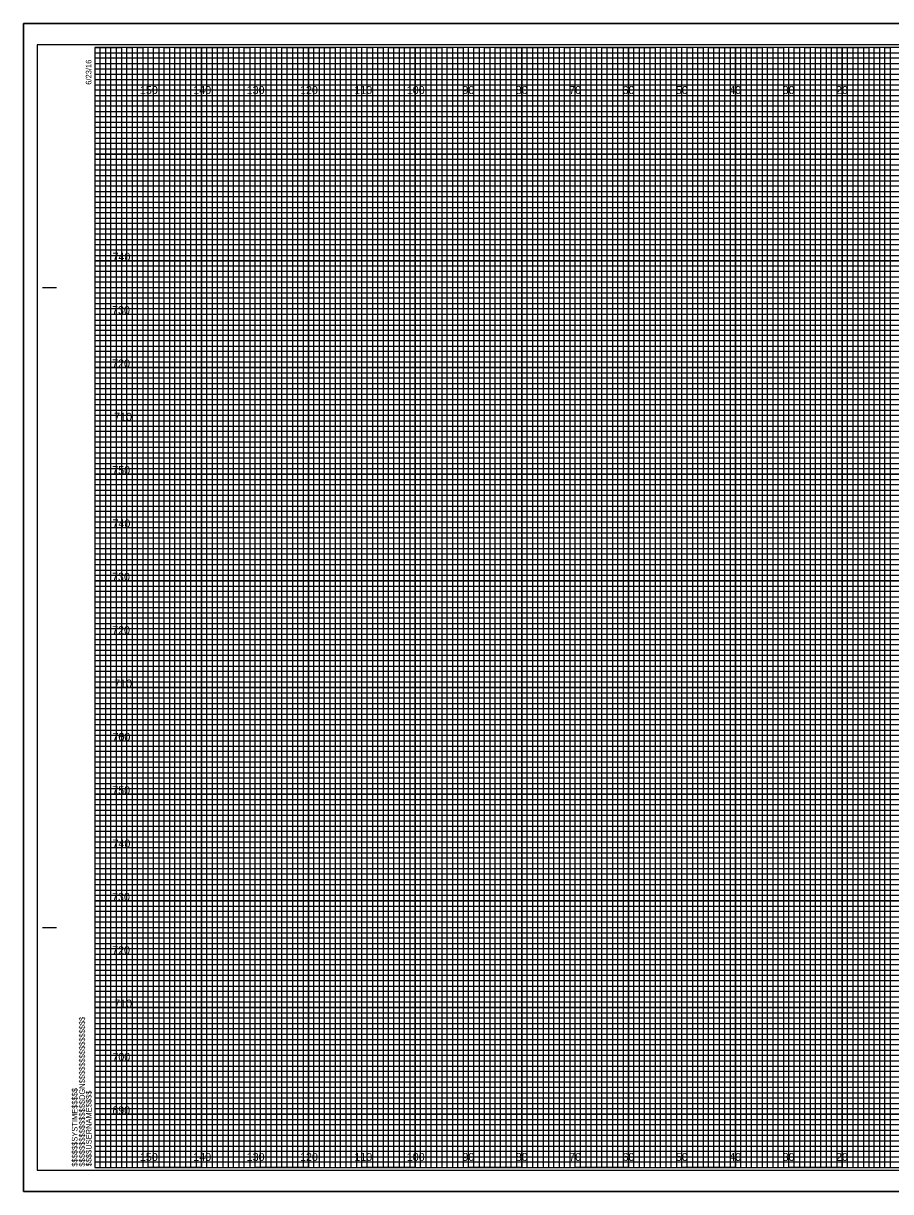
# Model space of a CAD drawing. Extents: x -98 to 717, y -10 to 1974.
# Drawn here: x -13.4 to 149.1, y 1315.5 to 1534.5 of the extents above; entities that cross this region are included whole.
import ezdxf

# ---------------------------------------------------------------- set-up
doc = ezdxf.new("R2010")
doc.units = 0
for name, color, linetype in [('Default', 7, 'Continuous'), ('Exist XS Center Line Elevation Label', 7, 'Continuous'), ('Prop CMT Conc Surface', 7, 'Continuous'), ('Prop CMT Concrete Structures', 7, 'Continuous'), ('Prop CMT Pvmt Course 1 CG', 7, 'Continuous'), ('Prop CMT Pvmt Course 2', 7, 'Continuous'), ('Prop CMT Pvmt Course 3', 7, 'Continuous'), ('Prop CMT Pvmt Surface', 7, 'Continuous'), ('Prop CMT Subgrade Earthwork', 7, 'Continuous'), ('Prop XS Earthwork Shape', 7, 'Continuous'), ('Prop XS Elevation Labels', 7, 'Continuous'), ('Typical Curb CELL', 7, 'Continuous')]:
    doc.layers.add(name, color=color, linetype=linetype)

msp = doc.modelspace()

# ---------------------------------------------------------------- linework, layer by layer
at = {"layer": 'Default'}
msp.add_lwpolyline([(323.3, 1315.5), (-13.4, 1315.5), (-13.4, 1534.5), (323.3, 1534.5)], close=True, dxfattribs=at)
at = {"layer": 'Exist XS Center Line Elevation Label'}
for p, q in [((0, 1529), (260, 1529)), ((260, 1527.98), (0, 1527.98)), ((0, 1527.98), (0, 1527)), ((0, 1527), (260, 1527)), ((260, 1525.89), (0, 1525.89)), ((0, 1525.89), (0, 1524)), ((0, 1524), (320, 1524))]:
    msp.add_line(p, q, dxfattribs=at)
for points in [[(0, 1523), (270, 1523), (320, 1523), (320, 1522), (0, 1522)], [(0, 1521), (320, 1521), (320, 1519), (0, 1519)], [(0, 1518), (320, 1518), (320, 1517), (0, 1516.98)], [(0, 1516), (320, 1516), (320, 1514), (0, 1514)], [(0, 1513), (320, 1513), (320, 1512), (0, 1512)], [(0, 1511), (320, 1511), (320, 1509), (0, 1509)], [(0, 1508), (320, 1508), (320, 1507), (0, 1507)], [(0, 1506), (320, 1506), (320, 1504), (0, 1504)], [(0, 1503), (320, 1503), (320, 1502), (0, 1502)], [(0, 1501), (320, 1501), (320, 1499), (0, 1499)], [(0, 1498), (320, 1498), (320, 1497), (0, 1497)], [(0, 1496), (320, 1496), (320, 1493.95), (320, 1493), (320, 1492), (0, 1492)], [(0, 1494), (320, 1494), (320, 1493), (0, 1493)], [(0, 1491), (320, 1491), (320, 1489), (0, 1489.03)], [(0, 1489.03), (320, 1489), (320, 1488), (0, 1488)], [(0, 1487), (320, 1487), (320, 1486), (0, 1486)], [(0, 1484), (320, 1484), (320, 1483), (0, 1483)], [(0, 1482), (320, 1482), (320, 1481), (0, 1481)], [(-0.07, 1478.89), (320, 1478.89), (320, 1477.88), (-0.07, 1477.88)], [(0, 1477), (320, 1477), (320, 1476), (0, 1476)], [(0, 1474), (320, 1474), (320, 1473), (0, 1473)], [(0, 1472), (320, 1472), (320, 1471), (0, 1471)], [(0, 1469), (320, 1469), (320, 1468), (0, 1468)], [(0, 1467), (320, 1467), (320, 1466), (0, 1466)], [(0, 1464), (320, 1464), (320, 1463), (0, 1463)], [(0, 1462), (320, 1462), (320, 1461), (0, 1461)], [(0, 1459), (320, 1459), (319.99, 1457.98), (0, 1458)], [(0, 1457), (320, 1457), (320, 1456), (0, 1456)], [(0, 1454), (320, 1454), (320, 1453), (0, 1453)], [(0, 1452), (320, 1452), (320, 1451), (0, 1451)], [(0, 1449), (320, 1449), (320, 1448), (0, 1448)], [(0, 1447), (320, 1447), (320, 1446), (0, 1446)], [(0, 1444), (320, 1444), (320, 1443), (0, 1443)], [(0, 1442), (320, 1442), (320, 1441), (0, 1441)], [(0, 1439), (320, 1439), (320, 1438), (0, 1438)], [(0, 1436.99), (320.07, 1436.91), (320, 1436), (0, 1436)], [(0, 1434), (320, 1434), (320, 1433), (0, 1433)], [(0, 1432), (320, 1432), (320, 1431), (0, 1431)], [(0, 1429), (320, 1429), (320, 1428), (0, 1428)], [(0, 1427), (320, 1427), (320, 1426), (0, 1426)], [(0, 1424), (320, 1424), (320, 1423), (0, 1423)], [(0, 1422), (320, 1422), (320, 1421), (0, 1421)], [(0, 1419), (320, 1419), (320, 1418), (0, 1418)], [(0, 1417), (320, 1417), (320, 1416), (0, 1416)], [(0, 1414), (320, 1414), (320, 1413), (0, 1413)], [(0, 1412), (320, 1412), (320, 1411), (0, 1411)], [(0, 1409), (320, 1409), (320, 1408), (0, 1408)], [(0, 1407), (320, 1407), (320, 1406), (0, 1406)], [(0, 1404), (320, 1404), (320, 1403), (0, 1403)], [(0, 1402), (320, 1402), (320, 1401), (0, 1401)], [(0, 1399), (320, 1399), (319.99, 1397.98), (0, 1398)], [(0, 1397), (320, 1397), (320, 1396), (0, 1396)], [(0, 1394), (320, 1394), (320, 1393), (0, 1393)], [(0, 1392), (320, 1392), (320, 1391), (0, 1391)], [(0, 1389), (320, 1389), (320, 1388), (0, 1388)], [(0, 1387), (320, 1387), (320, 1386), (0, 1386)], [(0, 1384), (320, 1384), (320, 1383), (0, 1383)], [(0, 1382), (320, 1382), (320, 1381), (0, 1381)], [(0, 1379), (320, 1379), (320, 1378), (0, 1378)], [(0, 1376.99), (320.07, 1376.91), (320, 1376), (0, 1376)], [(0, 1374), (320, 1374), (320, 1373), (0, 1373)], [(0, 1372), (320, 1372), (320, 1371), (0, 1371)], [(0, 1369), (320, 1369), (320, 1368), (0, 1368)], [(0, 1367), (320, 1367), (320, 1366), (0, 1366)], [(0, 1364), (320, 1364), (320, 1363), (0, 1363)], [(0, 1362), (320, 1362), (320, 1361), (0, 1361)], [(0, 1359), (320, 1359), (320, 1358), (0, 1358)], [(0, 1357), (320, 1357), (320, 1356), (0, 1356)], [(0, 1354), (320, 1354), (320, 1353), (0, 1353)], [(0, 1352), (320, 1352), (320, 1351), (0, 1351)], [(0, 1349), (320, 1349), (320, 1348), (0, 1348)], [(0, 1347), (320, 1347), (320, 1346), (0, 1346)], [(0, 1344), (320, 1344), (320, 1343), (0, 1343)], [(0, 1342), (320, 1342), (320, 1341), (0, 1341)], [(0, 1339), (320, 1339), (320, 1338), (0, 1338)], [(0, 1337), (320, 1337), (320, 1336), (0, 1336)], [(0, 1334), (320, 1334), (320, 1333), (0, 1333)], [(0, 1332), (320, 1332), (320, 1331), (0, 1331)], [(0, 1329), (320, 1329), (320, 1328), (0, 1328)], [(0, 1327), (320, 1327), (320, 1326), (0, 1326)], [(0, 1324), (320, 1324), (320, 1323), (0, 1323)], [(0, 1322), (320, 1322), (320, 1321), (0, 1321)]]:
    msp.add_lwpolyline(points, dxfattribs=at)
at = {"layer": 'Prop CMT Conc Surface'}
for p, q in [((-9.8, 1485), (-7.3, 1485)), ((-9.7, 1485), (-7.2, 1485)), ((-9.8, 1365), (-7.3, 1365)), ((-9.7, 1365), (-7.2, 1365)), ((0, 1320), (0, 1320)), ((0, 1320), (0, 1320)), ((0, 1320), (0, 1320)), ((0, 1320), (0, 1320)), ((0, 1320), (0, 1320)), ((0, 1320), (0, 1320)), ((0, 1320), (0, 1320))]:
    msp.add_line(p, q, dxfattribs=at)
msp.add_lwpolyline([(320, 1530), (0, 1530), (0, 1320), (320, 1320)], close=True, dxfattribs=at)
at = {"layer": 'Prop CMT Concrete Structures'}
for p, q in [((10, 1320), (10, 1530)), ((20, 1320), (20, 1530)), ((30, 1320), (30, 1530)), ((40, 1320), (40, 1530)), ((50, 1320), (50, 1530)), ((60, 1320), (60, 1530)), ((70, 1320), (70, 1530)), ((80, 1320), (80, 1530)), ((90, 1320), (90, 1530)), ((100, 1320), (100, 1530)), ((110, 1320), (110, 1530)), ((120, 1320), (120, 1530)), ((130, 1320), (130, 1530)), ((140, 1320), (140, 1530)), ((0, 1520), (320, 1520)), ((0, 1510), (320, 1510)), ((0, 1500), (320, 1500)), ((0, 1490), (320, 1490)), ((0, 1480), (320, 1480)), ((0, 1470), (320, 1470)), ((0, 1460), (320, 1460)), ((0, 1450), (320, 1450)), ((0, 1440), (320, 1440)), ((0, 1430), (320, 1430)), ((0, 1420), (320, 1420)), ((0, 1410), (320, 1410)), ((0, 1400), (320, 1400)), ((0, 1390), (320, 1390)), ((0, 1380), (320, 1380)), ((0, 1370), (320, 1370)), ((0, 1360), (320, 1360)), ((0, 1350), (320, 1350)), ((0, 1340), (320, 1340)), ((0, 1330), (320, 1330))]:
    msp.add_line(p, q, dxfattribs=at)
at = {"layer": 'Prop CMT Pvmt Course 2'}
msp.add_lwpolyline([(-13.4, 1315.5), (323.3, 1315.5), (323.3, 1534.5), (-13.4, 1534.5)], close=True, dxfattribs=at)
at = {"layer": 'Prop CMT Pvmt Course 3'}
msp.add_lwpolyline([(-10.8, 1319.5), (322.4, 1319.5), (322.4, 1530.5), (-10.8, 1530.5)], close=True, dxfattribs=at)
at = {"layer": 'Prop CMT Pvmt Surface'}
for p, q in [((323.3, 1534.5), (-13.4, 1534.5)), ((-13.4, 1534.5), (-13.4, 1315.5)), ((-13.4, 1315.5), (323.3, 1315.5))]:
    msp.add_line(p, q, dxfattribs=at)
at = {"layer": 'Prop CMT Subgrade Earthwork'}
for points in [[(0, 1320), (1, 1320), (1, 1530), (2, 1530), (2, 1320)], [(2, 1320), (3, 1320), (3, 1530), (4, 1530), (4, 1320)], [(5, 1320), (6, 1320), (6, 1530), (7, 1530), (7, 1320)], [(7, 1320), (8, 1320), (8, 1530), (9, 1530), (9, 1320)], [(10, 1320), (11, 1320), (11, 1530), (12, 1530), (12, 1320)], [(12, 1320), (13, 1320), (13, 1530), (14, 1530), (14, 1320)], [(15, 1320), (16, 1320), (16, 1530), (17, 1530), (17, 1320)], [(17, 1320), (18, 1320), (18, 1530), (19, 1530), (19, 1320)], [(20, 1320), (21, 1320), (21, 1530), (22, 1530), (22, 1320)], [(22, 1320), (23, 1320), (23, 1530), (24, 1530), (24, 1320)], [(25, 1320), (26, 1320), (26, 1530), (27, 1530), (27, 1320)], [(27, 1320), (28, 1320), (28, 1530), (29, 1530), (29, 1320)], [(30, 1320), (31, 1320), (31, 1530), (32, 1530), (32, 1320)], [(32, 1320), (33, 1320), (33, 1530), (34, 1530), (34, 1320)], [(35, 1320), (36, 1320), (36, 1530), (37, 1530), (37, 1320)], [(37, 1320), (38, 1320), (38, 1530), (39, 1530), (39, 1320)], [(40, 1320), (41, 1320), (41, 1530), (42, 1530), (42, 1320)], [(42, 1320), (43, 1320), (43, 1530), (44, 1530), (44, 1320)], [(45, 1320), (46, 1320), (46, 1530), (47, 1530), (47, 1320)], [(47, 1320), (48, 1320), (48, 1530), (49, 1530), (49, 1320)], [(50, 1320), (51, 1320), (51, 1530), (52, 1530), (52, 1320)], [(52, 1320), (53, 1320), (53, 1530), (54, 1530), (54, 1320)], [(55, 1320), (56, 1320), (56, 1530), (57, 1530), (57, 1320)], [(57, 1320), (58, 1320), (58, 1530), (59, 1530), (59, 1320)], [(60, 1320), (61, 1320), (61, 1530), (62, 1530), (62, 1320)], [(62, 1320), (63, 1320), (63, 1530), (64, 1530), (64, 1320)], [(65, 1320), (66, 1320), (66, 1530), (67, 1530), (67, 1320)], [(67, 1320), (68, 1320), (68, 1530), (69, 1530), (69, 1320)], [(70, 1320), (71, 1320), (71, 1530), (72, 1530), (72, 1320)], [(72, 1320), (73, 1320), (73, 1530), (74, 1530), (74, 1320)], [(75, 1320), (76, 1320), (76, 1530), (77, 1530), (77, 1320)], [(77, 1320), (78, 1320), (78, 1530), (79, 1530), (79, 1320)], [(80, 1320), (81, 1320), (81, 1530), (82, 1530), (82, 1320)], [(82, 1320), (83, 1320), (83, 1530), (84, 1530), (84, 1320)], [(85, 1320), (86, 1320), (86, 1530), (87, 1530), (87, 1320)], [(87, 1320), (88, 1320), (88, 1530), (89, 1530), (89, 1320)], [(90, 1320), (91, 1320), (91, 1530), (92, 1530), (92, 1320)], [(92, 1320), (93, 1320), (93, 1530), (94, 1530), (94, 1320)], [(95, 1320), (96, 1320), (96, 1530), (97, 1530), (97, 1320)], [(97, 1320), (98, 1320), (98, 1530), (99, 1530), (99, 1320)], [(100, 1320), (101, 1320), (101, 1530), (102, 1530), (102, 1320)], [(102, 1320), (103, 1320), (103, 1530), (104, 1530), (104, 1320)], [(105, 1320), (106, 1320), (106, 1530), (107, 1530), (107, 1320)], [(107, 1320), (108, 1320), (108, 1530), (109, 1530), (109, 1320)], [(110, 1320), (111, 1320), (111, 1530), (112, 1530), (112, 1320)], [(112, 1320), (113, 1320), (113, 1530), (114, 1530), (114, 1320)], [(115, 1320), (116, 1320), (116, 1530), (117, 1530), (117, 1320)], [(117, 1320), (118, 1320), (118, 1530), (119, 1530), (119, 1320)], [(120, 1320), (121, 1320), (121, 1530), (122, 1530), (122, 1320)], [(122, 1320), (123, 1320), (123, 1530), (124, 1530), (124, 1320)], [(125, 1320), (126, 1320), (126, 1530), (127, 1530), (127, 1320)], [(127, 1320), (128, 1320), (128, 1530), (129, 1530), (129, 1320)], [(130, 1320), (131, 1320), (131, 1530), (132, 1530), (132, 1320)], [(132, 1320), (133, 1320), (133, 1530), (134, 1530), (134, 1320)], [(135, 1320), (136, 1320), (136, 1530), (137, 1530), (137, 1320)], [(137, 1320), (138, 1320), (138, 1530), (139, 1530), (139, 1320)], [(140, 1320), (141, 1320), (141, 1530), (142, 1530), (142, 1320)], [(142, 1320), (143, 1320), (143, 1530), (144, 1530), (144, 1320)], [(145, 1320), (146, 1320), (146, 1530), (147, 1530), (147, 1320)], [(147, 1320), (148, 1320), (148, 1530), (149, 1530), (149, 1320)]]:
    msp.add_lwpolyline(points, dxfattribs=at)
at = {"layer": 'Prop XS Elevation Labels'}
for p, q in [((10, 1530), (0, 1530)), ((10, 1320), (10, 1530)), ((30, 1530), (20, 1530)), ((20, 1530), (20, 1320)), ((30, 1320), (30, 1530)), ((50, 1530), (40, 1530)), ((40, 1530), (40, 1320)), ((50, 1320), (50, 1530)), ((70, 1530), (60, 1530)), ((60, 1530), (60, 1320)), ((70, 1320), (70, 1530)), ((90, 1530), (80, 1530)), ((80, 1530), (80, 1320)), ((90, 1320), (90, 1530)), ((110, 1530), (100, 1530)), ((100, 1530), (100, 1320)), ((110, 1320), (110, 1530)), ((130, 1530), (120, 1530)), ((120, 1530), (120, 1320)), ((130, 1320), (130, 1530)), ((150, 1530), (140, 1530)), ((140, 1530), (140, 1320)), ((20, 1320), (10, 1320)), ((40, 1320), (30, 1320)), ((60, 1320), (50, 1320)), ((80, 1320), (70, 1320)), ((100, 1320), (90, 1320)), ((120, 1320), (110, 1320)), ((140, 1320), (130, 1320))]:
    msp.add_line(p, q, dxfattribs=at)
for points in [[(0, 1520), (320, 1520), (320, 1510), (0, 1510)], [(0, 1500), (320, 1500), (320, 1490), (0, 1490)], [(0, 1480), (320, 1480), (320, 1470), (0, 1470)], [(0, 1460), (320, 1460), (320, 1450), (0, 1450)], [(0, 1440), (320, 1440), (320, 1430), (0, 1430)], [(0, 1420), (320, 1420), (320, 1410), (0, 1410)], [(0, 1400), (320, 1400), (320, 1390), (0, 1390)], [(0, 1380), (320, 1380), (320, 1370), (0, 1370)], [(0, 1360), (320, 1360), (320, 1350), (0, 1350)], [(0, 1340), (320, 1340), (320, 1330), (0, 1330)]]:
    msp.add_lwpolyline(points, dxfattribs=at)
at = {"layer": 'Typical Curb CELL'}
for points in [[(0, 1530), (5, 1530), (5, 1320), (15, 1320), (15, 1530), (25, 1530), (25, 1320), (35, 1320), (35, 1530), (45, 1530), (45, 1320), (55, 1320), (55, 1530), (65, 1530), (65, 1320), (75, 1320), (75, 1530), (85, 1530), (85, 1320), (95, 1320), (95, 1530), (105, 1530), (105, 1320), (115, 1320), (115, 1530), (125, 1530), (125, 1320), (135, 1320), (135, 1530), (145, 1530), (145, 1320), (155, 1320)], [(0, 1525), (275, 1525)], [(0, 1505), (320, 1505), (320, 1515), (0, 1515)], [(0, 1485), (320, 1485), (320, 1495), (0, 1495)], [(0, 1465), (320, 1465), (320, 1475), (0, 1475)], [(0, 1445), (320, 1445), (320, 1455), (0, 1455)], [(0, 1425), (320, 1425), (320, 1435), (0, 1435)], [(0, 1405), (320, 1405), (320, 1415), (0, 1415)], [(0, 1385), (320, 1385), (320, 1395), (0, 1395)], [(0, 1365), (320, 1365), (320, 1375), (0, 1375)], [(0, 1345), (320, 1345), (320, 1355), (0, 1355)], [(0, 1325), (320, 1325), (320, 1335), (0, 1335)]]:
    msp.add_lwpolyline(points, dxfattribs=at)

# ---------------------------------------------------------------- texts
at = {"layer": 'Prop CMT Conc Surface'}
for s, p in [('6/23/16', (-0.65, 1523)), ('$$$$$$$$$$$$$$$$DGN$$$$$$$$$$$$$$$$', (-1.88, 1320.18)), ('$$$$$$SYSTIME$$$$$', (-3.26, 1320.18)), ('$$$$USERNAME$$$$', (-0.62, 1320.23))]:
    msp.add_text(s, height=1.05, rotation=90, dxfattribs=at).set_placement(p)
at = {"layer": 'Prop CMT Pvmt Course 1 CG'}
for s, p in [('740', (3.3, 1490)), ('730', (3.22, 1480)), ('720', (3.23, 1470)), ('710', (3.61, 1460)), ('750', (3.25, 1450)), ('740', (3.3, 1440)), ('730', (3.22, 1430)), ('720', (3.23, 1420)), ('710', (3.61, 1410)), ('700', (3.28, 1400)), ('760', (3.3, 1400)), ('750', (3.25, 1390)), ('740', (3.3, 1380)), ('730', (3.22, 1370)), ('720', (3.23, 1360)), ('710', (3.61, 1350)), ('700', (3.28, 1340)), ('690', (3.26, 1330))]:
    msp.add_text(s, height=1.5, dxfattribs=at).set_placement(p)
at = {"layer": 'Prop XS Earthwork Shape'}
for s, p in [('150', (8.44, 1521.25)), ('140', (18.44, 1521.25)), ('130', (28.44, 1521.25)), ('120', (38.44, 1521.25)), ('110', (48.62, 1521.25)), ('100', (58.44, 1521.25)), ('90', (68.86, 1521.25)), ('80', (78.86, 1521.25)), ('70', (88.86, 1521.25)), ('60', (98.86, 1521.25)), ('50', (108.86, 1521.25)), ('40', (118.86, 1521.25)), ('30', (128.86, 1521.25)), ('20', (138.86, 1521.25)), ('150', (8.44, 1321.25)), ('140', (18.44, 1321.25)), ('130', (28.44, 1321.25)), ('120', (38.44, 1321.25)), ('110', (48.62, 1321.25)), ('100', (58.44, 1321.25)), ('90', (68.86, 1321.25)), ('80', (78.86, 1321.25)), ('70', (88.86, 1321.25)), ('60', (98.86, 1321.25)), ('50', (108.86, 1321.25)), ('40', (118.86, 1321.25)), ('30', (128.86, 1321.25)), ('20', (138.86, 1321.25))]:
    msp.add_text(s, height=1.5, dxfattribs=at).set_placement(p)

doc.saveas('drawing.dxf')
